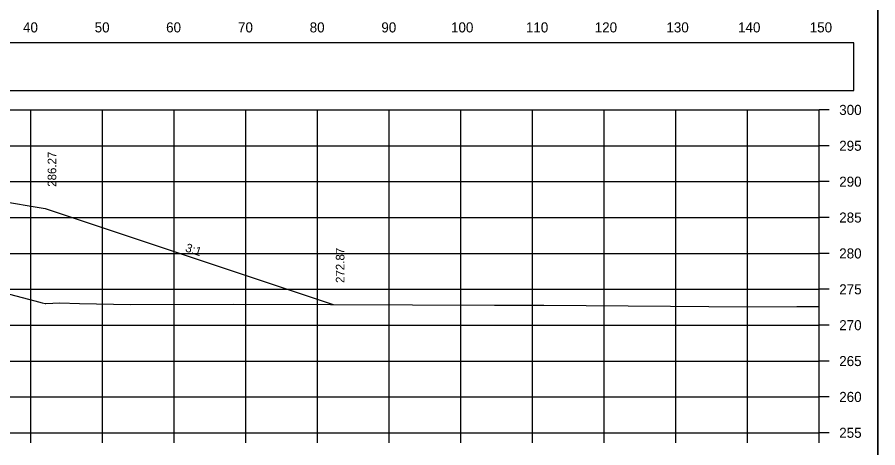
# Model space of a CAD drawing. Extents: x 285 to 4233, y -659 to 3710.
# Drawn here: x 2597.6 to 2717.7, y 3044.8 to 3104.8 of the extents above; entities that cross this region are included whole.
import ezdxf

# ---------------------------------------------------------------- set-up
doc = ezdxf.new("R2010")
doc.units = 0
for name, color, linetype in [('R_Axis', 7, 'Continuous'), ('R_Axis Annot', 7, 'Continuous'), ('R_Border', 7, 'Continuous'), ('R_Exist Surface', 7, 'Continuous'), ('R_Fin Surface', 7, 'Continuous'), ('R_Grid', 7, 'Continuous'), ('R_No Plot', 7, 'Continuous'), ('R_Xsect Elev', 7, 'Continuous'), ('R_Xsect Slope', 7, 'Continuous')]:
    doc.layers.add(name, color=color, linetype=linetype)

msp = doc.modelspace()

# ---------------------------------------------------------------- linework, layer by layer
at = {"layer": 'R_Axis'}
for p, q in [((2709.5, 3046.88), (2709.5, 3091.88)), ((2710.9, 3091.88), (2709.5, 3091.88)), ((2710.9, 3086.88), (2709.5, 3086.88)), ((2710.9, 3081.88), (2709.5, 3081.88)), ((2710.9, 3076.88), (2709.5, 3076.88)), ((2710.9, 3071.88), (2709.5, 3071.88)), ((2710.9, 3066.88), (2709.5, 3066.88)), ((2710.9, 3061.88), (2709.5, 3061.88)), ((2710.9, 3056.88), (2709.5, 3056.88)), ((2710.9, 3051.88), (2709.5, 3051.88)), ((2409.5, 3046.88), (2709.5, 3046.88)), ((2599.5, 3045.48), (2599.5, 3046.88)), ((2609.5, 3045.48), (2609.5, 3046.88)), ((2619.5, 3045.48), (2619.5, 3046.88)), ((2629.5, 3045.48), (2629.5, 3046.88)), ((2639.5, 3045.48), (2639.5, 3046.88)), ((2649.5, 3045.48), (2649.5, 3046.88)), ((2659.5, 3045.48), (2659.5, 3046.88)), ((2669.5, 3045.48), (2669.5, 3046.88)), ((2679.5, 3045.48), (2679.5, 3046.88)), ((2689.5, 3045.48), (2689.5, 3046.88)), ((2699.5, 3045.48), (2699.5, 3046.88)), ((2709.5, 3045.48), (2709.5, 3046.88)), ((2710.9, 3046.88), (2709.5, 3046.88))]:
    msp.add_line(p, q, dxfattribs=at)
at = {"layer": 'R_Axis Annot'}
msp.add_lwpolyline([(2573.96, 3094.57), (2714.32, 3094.57), (2714.32, 3101.22), (2573.96, 3101.22)], close=True, dxfattribs=at)
at = {"layer": 'R_Border'}
msp.add_line((2717.68, 2966.88), (2717.68, 3172.34), dxfattribs=at)
at = {"layer": 'R_Exist Surface'}
msp.add_lwpolyline([(2594.7, 3066.66), (2600.08, 3065.26), (2601.1, 3065), (2601.51, 3064.89), (2601.6, 3064.9), (2603.54, 3064.97), (2606.31, 3064.9), (2613.42, 3064.77), (2627.83, 3064.79), (2641.32, 3064.76), (2664.2, 3064.69), (2671.08, 3064.68), (2688.75, 3064.53), (2699.45, 3064.45), (2706.39, 3064.48), (2709.5, 3064.49)], dxfattribs=at)
at = {"layer": 'R_Fin Surface'}
msp.add_lwpolyline([(2483.97, 3065.43), (2505.5, 3072.6), (2529.5, 3076.6), (2535.5, 3077.17), (2547.5, 3078.3), (2571.5, 3080.55), (2573.5, 3080.74), (2581.5, 3081.49), (2601.5, 3078.16), (2641.71, 3064.76)], dxfattribs=at)
at = {"layer": 'R_Grid'}
for p, q in [((2409.5, 3091.88), (2709.5, 3091.88)), ((2599.5, 3046.88), (2599.5, 3091.88)), ((2609.5, 3046.88), (2609.5, 3091.88)), ((2619.5, 3046.88), (2619.5, 3091.88)), ((2629.5, 3046.88), (2629.5, 3091.88)), ((2639.5, 3046.88), (2639.5, 3091.88)), ((2649.5, 3046.88), (2649.5, 3091.88)), ((2659.5, 3046.88), (2659.5, 3091.88)), ((2669.5, 3046.88), (2669.5, 3091.88)), ((2679.5, 3046.88), (2679.5, 3091.88)), ((2689.5, 3046.88), (2689.5, 3091.88)), ((2699.5, 3046.88), (2699.5, 3091.88)), ((2709.5, 3046.88), (2709.5, 3091.88)), ((2409.5, 3086.88), (2709.5, 3086.88)), ((2409.5, 3081.88), (2709.5, 3081.88)), ((2409.5, 3076.88), (2709.5, 3076.88)), ((2409.5, 3071.88), (2709.5, 3071.88)), ((2409.5, 3066.88), (2709.5, 3066.88)), ((2409.5, 3061.88), (2709.5, 3061.88)), ((2409.5, 3056.88), (2709.5, 3056.88)), ((2409.5, 3051.88), (2709.5, 3051.88)), ((2409.5, 3046.88), (2709.5, 3046.88))]:
    msp.add_line(p, q, dxfattribs=at)
at = {"layer": 'R_No Plot'}
msp.add_lwpolyline([(2635.42, 3172.34), (2655.04, 3172.34), (2655.04, 3162.46), (2671.15, 3162.46), (2694.35, 3162.46), (2694.47, 3134.31), (2717.68, 3134.31), (2717.68, 2966.88), (2401.5, 2966.88), (2401.5, 3172.34)], close=True, dxfattribs=at)

# ---------------------------------------------------------------- texts
at = {"layer": 'R_Axis Annot'}
for s, p in [('40', (2598.41, 3102.68)), ('50', (2608.41, 3102.68)), ('60', (2618.38, 3102.68)), ('70', (2628.41, 3102.68)), ('80', (2638.41, 3102.68)), ('90', (2648.41, 3102.68)), ('100', (2658.13, 3102.68)), ('110', (2668.58, 3102.68)), ('120', (2678.18, 3102.68)), ('130', (2688.18, 3102.68)), ('140', (2698.18, 3102.68)), ('150', (2708.18, 3102.68)), ('300', (2712.3, 3091.18)), ('295', (2712.3, 3086.18)), ('290', (2712.3, 3081.18)), ('285', (2712.3, 3076.18)), ('280', (2712.3, 3071.18)), ('275', (2712.3, 3066.18)), ('270', (2712.3, 3061.18)), ('265', (2712.3, 3056.18)), ('260', (2712.3, 3051.18)), ('255', (2712.3, 3046.18))]:
    msp.add_text(s, height=1.4, dxfattribs=at).set_placement(p)
at = {"layer": 'R_Xsect Elev'}
for s, p in [('286.27', (2603.05, 3081.16)), ('272.87', (2643.26, 3067.76))]:
    msp.add_text(s, height=1.2, rotation=90, dxfattribs=at).set_placement(p)
at = {"layer": 'R_Xsect Slope'}
msp.add_text('3:1', height=1.2, rotation=341.5651, dxfattribs=at).set_placement((2620.97, 3072.19))

doc.saveas('drawing.dxf')
